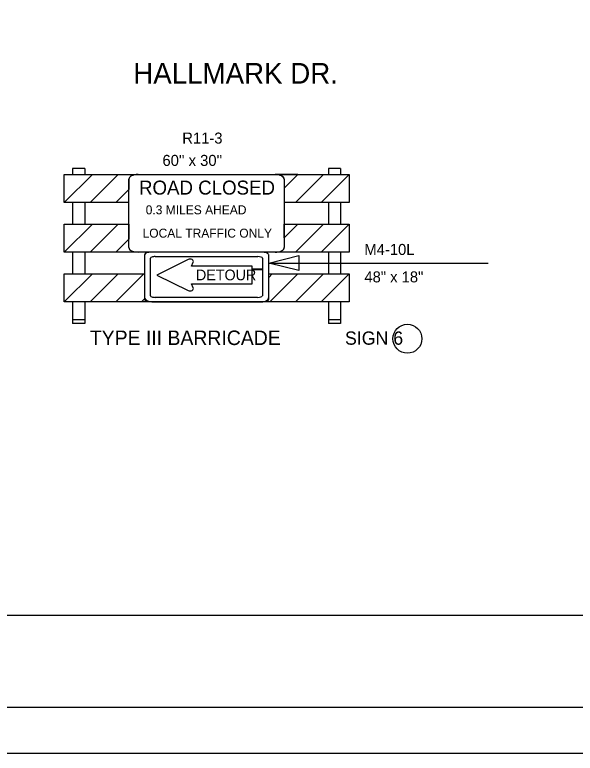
# Model space of a CAD drawing. Extents: x 1613335 to 1618399, y 897277 to 901877.
# Drawn here: x 1615143 to 1616057, y 898577 to 899781 of the extents above; entities that cross this region are included whole.
import ezdxf

# ---------------------------------------------------------------- set-up
doc = ezdxf.new("R2010")
doc.units = 0
for name, color, linetype in [('DEV BORDER CELL', 7, 'Continuous'), ('DEV TYPE 3 BARRICADE WITH R11-3 M4-10L CELL', 7, 'Continuous'), ('Old_Level_28', 7, 'Continuous'), ('Old_Level_8', 7, 'Continuous'), ('Scratch_Level_0', 7, 'Continuous'), ('Sheet Plot Border Outside CELL', 7, 'Continuous')]:
    doc.layers.add(name, color=color, linetype=linetype)

msp = doc.modelspace()

# ---------------------------------------------------------------- linework, layer by layer
at = {"layer": 'DEV BORDER CELL'}
msp.add_lwpolyline([(1618323.6, 901802.3), (1613823.6, 901802.3), (1613823.6, 898652.3), (1618323.6, 898652.3)], close=True, dxfattribs=at)
at = {"layer": 'DEV TYPE 3 BARRICADE WITH R11-3 M4-10L CELL'}
for p, q in [((1615257.3, 899530.5), (1615237.6, 899530.5)), ((1615237.6, 899530.5), (1615237.6, 899520.7)), ((1615257.3, 899530.5), (1615257.3, 899520.7)), ((1615674.2, 899530.5), (1615654.5, 899530.5)), ((1615654.5, 899530.5), (1615654.5, 899520.7)), ((1615674.2, 899530.5), (1615674.2, 899520.7)), ((1615223.8, 899520.7), (1615688, 899520.7)), ((1615223.8, 899475.2), (1615223.8, 899520.7)), ((1615223.8, 899475.2), (1615223.8, 899520.7)), ((1615223.8, 899520.7), (1615270.1, 899520.7)), ((1615270.1, 899520.7), (1615223.8, 899475.2)), ((1615266.4, 899475.2), (1615311.9, 899520.7)), ((1615311.9, 899520.7), (1615344.2, 899520.7)), ((1615329.4, 899513.3), (1615329.4, 899496.5)), ((1615604.5, 899520.7), (1615567.8, 899520.7)), ((1615582.4, 899498.6), (1615604.5, 899520.7)), ((1615582.4, 899513.3), (1615582.4, 899498.6)), ((1615582.4, 899513.3), (1615582.4, 899513.3)), ((1615600.8, 899475.2), (1615646.3, 899520.7)), ((1615688, 899520.7), (1615642.5, 899475.2)), ((1615646.3, 899520.7), (1615688, 899520.7)), ((1615688, 899520.7), (1615688, 899475.2)), ((1615329.4, 899496.5), (1615308.1, 899475.2)), ((1615329.4, 899475.2), (1615223.8, 899475.2)), ((1615237.6, 899475.2), (1615237.6, 899439.7)), ((1615257.3, 899475.2), (1615257.3, 899439.7)), ((1615308.1, 899475.2), (1615266.4, 899475.2)), ((1615688, 899475.2), (1615582.4, 899475.2)), ((1615642.5, 899475.2), (1615600.8, 899475.2)), ((1615654.5, 899475.2), (1615654.5, 899439.7)), ((1615674.2, 899475.2), (1615674.2, 899439.7)), ((1615223.8, 899394.2), (1615223.8, 899439.7)), ((1615223.8, 899394.2), (1615223.8, 899439.7)), ((1615223.8, 899439.7), (1615270.1, 899439.7)), ((1615270.1, 899439.7), (1615223.8, 899394.2)), ((1615223.8, 899439.7), (1615329.4, 899439.7)), ((1615266.4, 899394.2), (1615311.9, 899439.7)), ((1615311.9, 899439.7), (1615329.4, 899439.7)), ((1615582.4, 899439.7), (1615688, 899439.7)), ((1615582.4, 899417.6), (1615582.4, 899439.7)), ((1615582.4, 899439.7), (1615604.5, 899439.7)), ((1615604.5, 899439.7), (1615582.4, 899417.6)), ((1615600.8, 899394.2), (1615646.3, 899439.7)), ((1615688, 899439.7), (1615642.5, 899394.2)), ((1615646.3, 899439.7), (1615688, 899439.7)), ((1615688, 899439.7), (1615688, 899394.2)), ((1615688, 899394.2), (1615223.8, 899394.2)), ((1615237.6, 899394.2), (1615237.6, 899358.7)), ((1615257.3, 899394.2), (1615257.3, 899358.7)), ((1615308.1, 899394.2), (1615266.4, 899394.2)), ((1615642.5, 899394.2), (1615600.8, 899394.2)), ((1615654.5, 899394.2), (1615654.5, 899358.7)), ((1615674.2, 899394.2), (1615674.2, 899358.7)), ((1615364.6, 899323.1), (1615364.6, 899384.4)), ((1615372.1, 899386.9), (1615539.3, 899387.1)), ((1615425.9, 899382.3), (1615374.7, 899356.7)), ((1615547, 899384.4), (1615547, 899366.5)), ((1615431.2, 899371.3), (1615434.2, 899377.8)), ((1615530.2, 899371.3), (1615431.2, 899371.3)), ((1615530.2, 899366.5), (1615530.2, 899371.3)), ((1615557.1, 899376.5), (1615914.6, 899376.5)), ((1615223.8, 899313.2), (1615223.8, 899358.7)), ((1615223.8, 899358.7), (1615270.1, 899358.7)), ((1615270.1, 899358.7), (1615223.8, 899313.2)), ((1615223.8, 899313.2), (1615223.8, 899358.7)), ((1615223.8, 899358.7), (1615354.7, 899358.7)), ((1615266.4, 899313.2), (1615311.9, 899358.7)), ((1615353.7, 899358.7), (1615308.1, 899313.2)), ((1615311.9, 899358.7), (1615353.7, 899358.7)), ((1615374.7, 899356.7), (1615425.9, 899331.6)), ((1615547, 899366.5), (1615530.2, 899366.5)), ((1615530.2, 899342.4), (1615530.2, 899365.9)), ((1615530.2, 899365.9), (1615547, 899365.9)), ((1615547, 899365.9), (1615546.8, 899323.1)), ((1615557.1, 899353.1), (1615562.7, 899358.7)), ((1615557.1, 899358.7), (1615688, 899358.7)), ((1615604.5, 899358.7), (1615559, 899313.2)), ((1615562.7, 899358.7), (1615604.5, 899358.7)), ((1615600.8, 899313.2), (1615646.3, 899358.7)), ((1615688, 899358.7), (1615642.5, 899313.2)), ((1615646.3, 899358.7), (1615688, 899358.7)), ((1615688, 899358.7), (1615688, 899313.2)), ((1615557.1, 899320.6), (1615557.1, 899353.1)), ((1615434.2, 899336), (1615431.2, 899342.4)), ((1615431.2, 899342.4), (1615530.2, 899342.4)), ((1615539.1, 899320.5), (1615372.1, 899320.5)), ((1615688, 899313.2), (1615223.8, 899313.2)), ((1615237.6, 899313.2), (1615237.6, 899277.7)), ((1615257.3, 899313.2), (1615257.3, 899277.7)), ((1615308.1, 899313.2), (1615266.4, 899313.2)), ((1615349.9, 899313.2), (1615355.2, 899318.5)), ((1615366.5, 899313.2), (1615349.9, 899313.2)), ((1615366.5, 899313.2), (1615545.3, 899313.2)), ((1615559, 899313.2), (1615545.4, 899313.2)), ((1615642.5, 899313.2), (1615600.8, 899313.2)), ((1615654.5, 899313.2), (1615654.5, 899277.7)), ((1615674.2, 899313.2), (1615674.2, 899277.7)), ((1615257.3, 899283.7), (1615237.6, 899283.7)), ((1615674.2, 899283.7), (1615654.5, 899283.7)), ((1615257.3, 899277.7), (1615237.6, 899277.7)), ((1615674.2, 899277.7), (1615654.5, 899277.7))]:
    msp.add_line(p, q, dxfattribs=at)
for points in [[(1615329.4, 899401.6), (1615329.4, 899513.3)], [(1615344.2, 899520.7), (1615567.7, 899520.7)], [(1615582.4, 899513.3), (1615582.4, 899401.6)], [(1615329.4, 899439.7), (1615329.4, 899415.5), (1615308.1, 899394.2)], [(1615567.7, 899394.2), (1615344.2, 899394.2)], [(1615545.3, 899394.2), (1615366.5, 899394.2)], [(1615354.7, 899389.8), (1615354.7, 899317.6)], [(1615557.1, 899317.6), (1615557.1, 899389.8)]]:
    msp.add_lwpolyline(points, dxfattribs=at)
msp.add_lwpolyline([(1615606.4, 899364.2), (1615557.1, 899376.5), (1615606.4, 899388.8)], close=True, dxfattribs=at)
msp.add_lwpolyline([(1615606.4, 899364.2), (1615557.1, 899376.5), (1615606.4, 899388.8)], close=True, dxfattribs=at)
for centre, major_axis, ratio, start_param, end_param in [((1615344.2, 899513.3), (-14.8, 0), 0.5, 4.712162, 6.283185), ((1615344.2, 899513.3), (-14.8, 0), 0.5, 4.712162, 6.283185), ((1615567.7, 899513.3), (14.8, 0), 0.5, 0, 1.570881), ((1615567.7, 899513.3), (14.8, 0), 0.5, 0, 1.570796), ((1615344.2, 899401.6), (-14.8, 0), 0.5, 0, 1.570796), ((1615366.5, 899389.8), (-11.8, 0), 0.375009, 4.712389, 6.283185), ((1615545.3, 899389.8), (11.8, 0), 0.375009, 0, 1.571024), ((1615567.7, 899401.6), (-14.8, 0), 0.5, 1.570796, 3.141593), ((1615372.2, 899384.4), (-7.59, 0), 0.337508, 4.712198, 6.283193), ((1615429, 899378.9), (-5.42, 0), 0.720018, 2.830616, 5.313575), ((1615539.2, 899384.4), (7.59, 0), 0.337508, 6.283183, 7.85379), ((1615429, 899334.8), (-5.42, 0), 0.720018, 0.969609, 3.452568), ((1615372.1, 899323.1), (-7.59, 0), 0.337508, 0.000008, 1.570982), ((1615539.1, 899323.1), (7.59, 0), 0.337508, 4.712575, 6.283183), ((1615545.3, 899320.6), (-11.8, 0), 0.625, 1.570796, 3.141593), ((1615366.5, 899317.6), (11.8, 0), 0.375009, 3.141593, 4.712389), ((1615366.5, 899320.6), (-11.8, 0), 0.625, 0.287132, 1.570688), ((1615545.3, 899317.6), (11.8, 0), 0.375009, 4.712389, 6.283185)]:
    msp.add_ellipse(centre, major_axis=major_axis, ratio=ratio, start_param=start_param, end_param=end_param, dxfattribs=at)
at = {"layer": 'Old_Level_28'}
msp.add_circle((1615783.1, 899253.1), 23.6, dxfattribs=at)
at = {"layer": 'Scratch_Level_0'}
msp.add_lwpolyline([(1618173.6, 901652.3), (1613973.6, 901652.3), (1613973.6, 898802.3), (1616610.1, 898802.3), (1616610.1, 899157.1), (1618173.6, 899157.1)], close=True, dxfattribs=at)
at = {"layer": 'Sheet Plot Border Outside CELL'}
msp.add_lwpolyline([(1613334.6, 898577.3), (1618398.6, 898577.3), (1618398.6, 901877.3), (1613334.6, 901877.3)], close=True, dxfattribs=at)

# ---------------------------------------------------------------- texts
at = {"layer": 'DEV TYPE 3 BARRICADE WITH R11-3 M4-10L CELL'}
for s, height, p in [('R11-3', 18, (1615416.3, 899571.2)), ("60'' x 30''", 18, (1615384, 899534.8)), ('ROAD CLOSED', 22.762, (1615345.8, 899488.1)), ('0.3 MILES AHEAD', 14.631, (1615356.7, 899455.9)), ('LOCAL TRAFFIC ONLY', 14.631, (1615351.6, 899417.9)), ('M4-10L', 18, (1615713, 899389.6)), ('DETOUR', 17.4, (1615438.6, 899348.4)), ('48" x 18"', 18, (1615713, 899344.9)), ('TYPE III BARRICADE', 23.645, (1615265.7, 899242.8))]:
    msp.add_text(s, height=height, dxfattribs=at).set_placement(p)
at = {"layer": 'Old_Level_28'}
msp.add_text('SIGN 6', height=21.6, dxfattribs=at).set_placement((1615681.4, 899243.3))
at = {"layer": 'Old_Level_8'}
msp.add_text('HALLMARK DR.', height=33.75, dxfattribs=at).set_placement((1615336.4, 899668.9))

doc.saveas('drawing.dxf')
